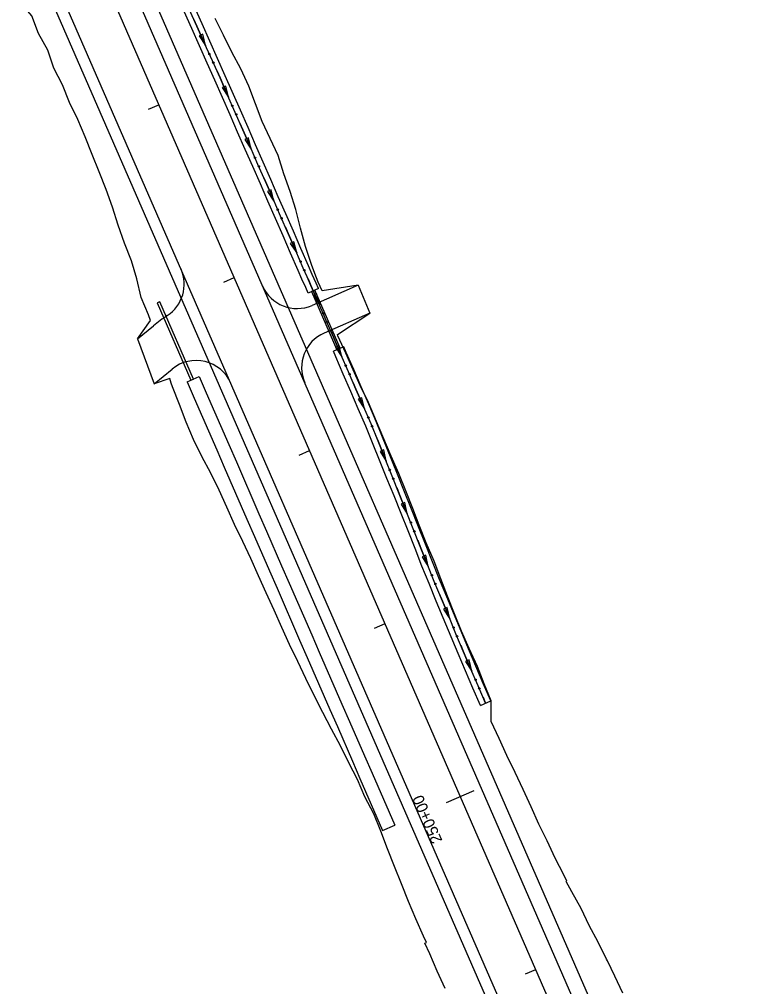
# Model space of a CAD drawing. Extents: x 948761 to 996004, y 1858548 to 1925175.
# Drawn here: x 964875 to 965260, y 1899394 to 1899906 of the extents above; entities that cross this region are included whole.
import ezdxf

# ---------------------------------------------------------------- set-up
doc = ezdxf.new("R2010")
doc.units = 0
for name, color, linetype in [('62', 7, 'Continuous'), ('R_Drainage', 7, 'Continuous'), ('R_Horz Alg', 7, 'Continuous'), ('R_Horz Alg Annot', 7, 'Continuous'), ('R_Proposed Const Limits', 7, 'Continuous'), ('R_Proposed Road', 7, 'Continuous')]:
    doc.layers.add(name, color=color, linetype=linetype)

msp = doc.modelspace()

# ---------------------------------------------------------------- linework, layer by layer
at = {"layer": '62'}
for p, q in [((964972.07, 1899898.53), (964970.13, 1899897.67)), ((964970.13, 1899897.67), (964973.56, 1899892.63)), ((964973.56, 1899892.63), (964972.07, 1899898.53)), ((964984.3, 1899871.09), (964982.36, 1899870.24)), ((964985.75, 1899865.17), (964984.3, 1899871.09)), ((964982.36, 1899870.24), (964985.75, 1899865.17)), ((964996.38, 1899843.59), (964994.45, 1899842.74)), ((964994.45, 1899842.74), (964997.83, 1899837.67)), ((964997.83, 1899837.67), (964996.38, 1899843.59)), ((965008.42, 1899816.07), (965006.48, 1899815.22)), ((965006.48, 1899815.22), (965009.85, 1899810.14)), ((965009.85, 1899810.14), (965008.42, 1899816.07)), ((965020.45, 1899788.54), (965018.51, 1899787.69)), ((965021.88, 1899782.62), (965020.45, 1899788.54)), ((965018.51, 1899787.69), (965021.88, 1899782.62)), ((965033.41, 1899763.74), (965027.91, 1899761.34)), ((965032.48, 1899761.02), (965030.54, 1899760.17)), ((965030.54, 1899760.17), (965033.9, 1899755.09)), ((965033.9, 1899755.09), (965032.48, 1899761.02)), ((965046.82, 1899732.91), (965041.31, 1899730.52)), ((965044.46, 1899733.47), (965042.52, 1899732.63)), ((965042.52, 1899732.63), (965045.88, 1899727.55)), ((965045.88, 1899727.55), (965044.46, 1899733.47)), ((964963.78, 1899714.27), (964970.19, 1899717.06)), ((965056.42, 1899705.92), (965054.48, 1899705.07)), ((965054.48, 1899705.07), (965057.83, 1899699.99)), ((965057.83, 1899699.99), (965056.42, 1899705.92)), ((965068.03, 1899678.19), (965066.06, 1899677.39)), ((965066.06, 1899677.39), (965069.29, 1899672.23)), ((965069.29, 1899672.23), (965068.03, 1899678.19)), ((965079.27, 1899650.33), (965077.3, 1899649.54)), ((965080.51, 1899644.36), (965079.27, 1899650.33)), ((965077.3, 1899649.54), (965080.51, 1899644.36)), ((965090.38, 1899622.42), (965088.41, 1899621.63)), ((965088.41, 1899621.63), (965091.61, 1899616.45)), ((965091.61, 1899616.45), (965090.38, 1899622.42)), ((965101.71, 1899594.62), (965099.76, 1899593.81)), ((965099.76, 1899593.81), (965103.04, 1899588.67)), ((965103.04, 1899588.67), (965101.71, 1899594.62)), ((965113.28, 1899566.9), (965111.33, 1899566.07)), ((965111.33, 1899566.07), (965114.66, 1899560.97)), ((965114.66, 1899560.97), (965113.28, 1899566.9)), ((965119.26, 1899542.81), (965124.77, 1899545.19)), ((965067.41, 1899476.56), (965073.82, 1899479.35))]:
    msp.add_line(p, q, dxfattribs=at)
for points in [[(965122.01, 1899544), (965118.04, 1899553.18), (965114.07, 1899562.35), (965110.14, 1899571.55), (965106.31, 1899580.79), (965102.47, 1899590.03), (965098.64, 1899599.26), (965094.81, 1899608.5), (965091.08, 1899617.78), (965087.38, 1899627.08), (965083.68, 1899636.38), (965079.99, 1899645.68), (965076.28, 1899654.97), (965072.52, 1899664.24), (965068.77, 1899673.51), (965065.02, 1899682.79), (965061.27, 1899692.06), (965057.29, 1899701.24), (965053.31, 1899710.41), (965049.33, 1899719.58), (965045.35, 1899728.76), (965041.37, 1899737.93), (965037.38, 1899747.1), (965036.58, 1899748.93), (965033.39, 1899756.27), (965029.4, 1899765.44), (965027.4, 1899770.02), (965025.39, 1899774.6), (965021.38, 1899783.76), (965017.38, 1899792.92), (965013.37, 1899802.09), (965009.37, 1899811.25), (965005.37, 1899820.42), (965001.37, 1899829.58), (964997.36, 1899838.74), (964993.34, 1899847.9), (964989.31, 1899857.05), (964985.29, 1899866.21), (964981.27, 1899875.36), (964977.2, 1899884.5), (964973.11, 1899893.62), (964969.01, 1899902.75), (964964.92, 1899911.87)], [(965033.41, 1899763.74), (965032.15, 1899766.64), (965030.14, 1899771.22), (965028.14, 1899775.8), (965024.13, 1899784.96), (965020.12, 1899794.13), (965016.12, 1899803.29), (965012.12, 1899812.45), (965008.12, 1899821.62), (965004.12, 1899830.78), (965000.11, 1899839.95), (964996.08, 1899849.1), (964992.06, 1899858.26), (964984.01, 1899876.58), (964979.94, 1899885.72), (964975.85, 1899894.85), (964971.75, 1899903.98), (964967.66, 1899913.1)], [(965027.91, 1899761.34), (965026.65, 1899764.24), (965024.65, 1899768.82), (965022.64, 1899773.4), (965018.63, 1899782.56), (965014.63, 1899791.72), (965010.62, 1899800.88), (965006.62, 1899810.05), (965002.62, 1899819.21), (964998.62, 1899828.38), (964994.61, 1899837.54), (964990.59, 1899846.69), (964986.57, 1899855.85), (964978.53, 1899874.15), (964974.46, 1899883.27), (964970.37, 1899892.4), (964966.28, 1899901.52), (964962.18, 1899910.65)], [(964967.4, 1899906.35), (964967.42, 1899906.31)], [(964967.42, 1899906.31), (964969.01, 1899902.75), (964973.11, 1899893.62), (964973.56, 1899892.63)], [(964979.68, 1899878.93), (964979.7, 1899878.9)], [(964979.7, 1899878.9), (964981.27, 1899875.36), (964985.29, 1899866.21), (964985.75, 1899865.17)], [(964991.78, 1899851.44), (964991.8, 1899851.41)], [(964991.8, 1899851.41), (964993.34, 1899847.9), (964997.36, 1899838.74), (964997.83, 1899837.67)], [(965003.83, 1899823.93), (965003.85, 1899823.89)], [(965003.85, 1899823.89), (965005.37, 1899820.42), (965009.37, 1899811.25), (965009.85, 1899810.14)], [(965015.86, 1899796.4), (965015.87, 1899796.36)], [(965015.87, 1899796.36), (965017.38, 1899792.92), (965021.38, 1899783.76), (965021.88, 1899782.62)], [(965027.89, 1899768.88), (965027.91, 1899768.85)], [(965027.91, 1899768.84), (965029.4, 1899765.44), (965033.39, 1899756.27), (965033.9, 1899755.09)], [(965039.88, 1899741.34), (965039.9, 1899741.3)], [(965039.9, 1899741.3), (965041.37, 1899737.93), (965045.35, 1899728.76), (965045.88, 1899727.55)], [(965124.77, 1899545.19), (965120.79, 1899554.37), (965116.82, 1899563.54), (965112.91, 1899572.71), (965101.41, 1899600.41), (965097.58, 1899609.63), (965093.86, 1899618.9), (965090.17, 1899628.19), (965086.47, 1899637.49), (965082.77, 1899646.79), (965079.06, 1899656.08), (965075.31, 1899665.36), (965064.04, 1899693.22), (965060.05, 1899702.43), (965056.07, 1899711.6), (965052.09, 1899720.78), (965048.1, 1899729.95), (965046.82, 1899732.91)], [(965119.26, 1899542.81), (965115.29, 1899551.98), (965111.31, 1899561.17), (965107.38, 1899570.39), (965095.87, 1899598.11), (965092.03, 1899607.37), (965088.29, 1899616.67), (965084.59, 1899625.97), (965080.9, 1899635.27), (965077.2, 1899644.56), (965073.49, 1899653.85), (965069.74, 1899663.12), (965058.51, 1899690.9), (965054.54, 1899700.04), (965050.56, 1899709.22), (965046.58, 1899718.39), (965042.6, 1899727.56), (965041.31, 1899730.52)], [(964970.19, 1899717.06), (964973.92, 1899708.52), (964985.91, 1899681.02), (964989.9, 1899671.86), (965001.89, 1899644.36), (965005.89, 1899635.19), (965013.88, 1899616.86), (965017.88, 1899607.69), (965029.86, 1899580.19), (965033.86, 1899571.02), (965045.85, 1899543.52), (965049.85, 1899534.36), (965057.84, 1899516.02), (965061.84, 1899506.85), (965073.82, 1899479.35)], [(964963.78, 1899714.27), (964967.5, 1899705.73), (964979.49, 1899678.23), (964983.49, 1899669.06), (964995.47, 1899641.56), (964999.47, 1899632.39), (965007.46, 1899614.06), (965011.46, 1899604.89), (965023.45, 1899577.39), (965027.45, 1899568.23), (965039.43, 1899540.72), (965043.43, 1899531.56), (965051.42, 1899513.22), (965055.42, 1899504.06), (965067.41, 1899476.56)], [(965051.85, 1899713.79), (965051.86, 1899713.75)], [(965051.86, 1899713.75), (965053.31, 1899710.41), (965057.29, 1899701.24), (965057.83, 1899699.99)], [(965063.66, 1899686.17), (965063.67, 1899686.13)], [(965063.67, 1899686.13), (965065.02, 1899682.79), (965068.77, 1899673.51), (965069.29, 1899672.23)], [(965074.92, 1899658.32), (965074.93, 1899658.29)], [(965074.93, 1899658.29), (965076.28, 1899654.97), (965079.99, 1899645.68), (965080.51, 1899644.36)], [(965086.05, 1899630.42), (965086.07, 1899630.39)], [(965086.07, 1899630.39), (965087.38, 1899627.08), (965091.08, 1899617.78), (965091.61, 1899616.45)], [(965097.27, 1899602.56), (965097.29, 1899602.52)], [(965097.29, 1899602.52), (965098.64, 1899599.26), (965102.47, 1899590.03), (965103.04, 1899588.67)], [(965108.79, 1899574.82), (965108.8, 1899574.78)], [(965108.8, 1899574.78), (965110.14, 1899571.55), (965114.07, 1899562.35), (965114.66, 1899560.97)], [(965120.62, 1899547.21), (965120.64, 1899547.17)], [(965120.64, 1899547.17), (965122.01, 1899544)]]:
    msp.add_lwpolyline(points, dxfattribs=at)
for centre in [(964975.64, 1899888.07), (964977.69, 1899883.5), (964987.79, 1899860.6), (964989.81, 1899856.02), (964999.87, 1899833.1), (965001.87, 1899828.51), (965011.89, 1899805.57), (965013.89, 1899800.98), (965023.92, 1899778.05), (965025.93, 1899773.46), (965035.93, 1899750.52), (965037.93, 1899745.92), (965047.9, 1899722.97), (965049.9, 1899718.37), (965059.86, 1899695.41), (965061.82, 1899690.8), (965071.2, 1899667.6), (965073.08, 1899662.95), (965082.39, 1899639.72), (965084.24, 1899635.07), (965093.51, 1899611.82), (965095.39, 1899607.18), (965104.99, 1899584.06), (965106.91, 1899579.43), (965116.68, 1899556.39), (965118.68, 1899551.8)]:
    msp.add_circle(centre, 0.375, dxfattribs=at)
at = {"layer": 'R_Drainage'}
for p, q in [((965031.58, 1899762.94), (965029.75, 1899762.14)), ((965044.98, 1899732.12), (965031.58, 1899762.94)), ((965029.75, 1899762.14), (965043.15, 1899731.32)), ((964949.36, 1899756.72), (964947.98, 1899756.12)), ((964947.98, 1899756.12), (964965.84, 1899715.17)), ((964967.21, 1899715.77), (964949.36, 1899756.72)), ((965043.15, 1899731.32), (965044.98, 1899732.12)), ((964965.84, 1899715.17), (964967.21, 1899715.77))]:
    msp.add_line(p, q, dxfattribs=at)
at = {"layer": 'R_Horz Alg'}
msp.add_line((965242.02, 1899188.63), (964906.4, 1899958.5), dxfattribs=at)
at = {"layer": 'R_Horz Alg Annot'}
for points in [[(964943.31, 1899858.81), (964948.81, 1899861.21)], [(964983.27, 1899767.15), (964988.77, 1899769.54)], [(965023.23, 1899675.48), (965028.73, 1899677.88)], [(965063.2, 1899583.81), (965068.7, 1899586.21)], [(965101.32, 1899491.34), (965115.99, 1899497.74)], [(965143.12, 1899400.47), (965148.62, 1899402.87)]]:
    msp.add_lwpolyline(points, dxfattribs=at)
at = {"layer": 'R_Proposed Const Limits'}
for points in [[(964913.41, 1899834.87), (964909.82, 1899844.21), (964905.89, 1899853.41), (964901.53, 1899862.42), (964897.69, 1899871.65), (964893.15, 1899880.58), (964889.93, 1899890.09), (964885.04, 1899898.86), (964881.5, 1899908.23), (964874.9, 1899915.92)], [(965054.55, 1899765.49), (965035.36, 1899762.51), (965033.35, 1899767.16), (965031.47, 1899771.79), (965029.71, 1899776.48), (965026.59, 1899786.03), (965023.95, 1899795.79), (965021.45, 1899805.61), (965018.46, 1899815.21), (965015.05, 1899824.64), (965012.04, 1899834.23), (965007.84, 1899843.31), (965003.55, 1899852.35), (965000.09, 1899861.75), (964996.48, 1899871.09), (964992.34, 1899880.19), (964987.48, 1899888.98), (964983.18, 1899898.02), (964978.69, 1899906.97)], [(964937.5, 1899737.02), (964944.43, 1899746.81), (964943.41, 1899749.77), (964939.44, 1899758.95), (964937.16, 1899768.86), (964934.31, 1899778.53), (964930.63, 1899787.83), (964927.25, 1899797.27), (964924.18, 1899806.84), (964920.87, 1899816.3), (964917.28, 1899825.65), (964913.41, 1899834.87)], [(965124.94, 1899545.26), (965121.19, 1899554.2), (965117.67, 1899563.43), (965113.22, 1899572.92), (965109.29, 1899582.09), (965105.55, 1899591.37), (965101.89, 1899600.68), (965098.19, 1899609.98), (965094.66, 1899619.34), (965090.58, 1899628.98), (965086.81, 1899638.34), (965083.39, 1899647.16), (965079.71, 1899656.47), (965075.96, 1899665.74), (965072.02, 1899674.93), (965068.08, 1899684.12), (965064.14, 1899693.31), (965059.89, 1899703.33), (965055.46, 1899712.3), (965051.78, 1899720.71), (965047.88, 1899729.52), (965043.75, 1899738.75), (965043.52, 1899739.39), (965060.57, 1899750.66)], [(965100.49, 1899392.8), (965096.42, 1899401.93), (965092.44, 1899411.1), (965089.88, 1899416.85), (965089.88, 1899416.85), (965090.62, 1899417.19), (965089.06, 1899420.54), (965085.02, 1899429.69), (965081.16, 1899438.92), (965077.43, 1899448.2), (965073.69, 1899457.48), (965070.03, 1899466.79), (965066.5, 1899476.16), (965062.74, 1899485.43), (965058.03, 1899494.29), (965054.18, 1899503.52), (965049.55, 1899512.41), (965045.06, 1899521.36), (965040.31, 1899530.2), (965035.71, 1899539.1), (965031.12, 1899548.01), (965026.75, 1899557.01), (965022.41, 1899566.03), (965018.13, 1899575.07), (965014.01, 1899584.19), (965009.88, 1899593.29), (965005.79, 1899602.42), (965001.71, 1899611.55), (964997.58, 1899620.66), (964993.35, 1899629.73), (964988.93, 1899638.71), (964984.83, 1899647.83), (964980.73, 1899656.95), (964976.35, 1899665.95), (964971.63, 1899674.8), (964967.19, 1899683.78), (964963.35, 1899693.01), (964959.73, 1899702.34), (964956.14, 1899711.68), (964955.37, 1899713.53), (964954.65, 1899716.05), (964946.29, 1899713.17)], [(965181.62, 1899417.26), (965176.92, 1899426.12), (965172.63, 1899435.16), (965167.75, 1899443.94), (965164.67, 1899449.45), (965164.66, 1899449.46), (965165.1, 1899449.66), (965163.45, 1899452.97), (965158.85, 1899461.88), (965154.67, 1899470.96), (965150.25, 1899479.95), (965146.17, 1899489.07), (965141.98, 1899498.16), (965137.67, 1899507.19), (965133.27, 1899516.18), (965129.14, 1899525.29), (965124.96, 1899534.37), (965124.94, 1899545.26)], [(965194.79, 1899390.27), (965190.44, 1899399.28), (965186.59, 1899407.34), (965186.11, 1899408.3), (965181.62, 1899417.26)]]:
    msp.add_lwpolyline(points, dxfattribs=at)
at = {"layer": 'R_Proposed Road'}
for p, q in [((965253.02, 1899193.43), (964917.37, 1899963.34)), ((965260.35, 1899196.62), (964924.69, 1899966.58)), ((965220.02, 1899179.04), (964884.44, 1899948.8)), ((965214.52, 1899176.64), (964878.95, 1899946.38)), ((965054.55, 1899765.49), (965030.09, 1899754.83)), ((965054.55, 1899765.49), (965060.57, 1899750.66)), ((965060.57, 1899750.66), (965036.49, 1899740.16)), ((964937.5, 1899737.02), (964945.91, 1899743.94)), ((964937.5, 1899737.02), (964946.29, 1899713.17)), ((964946.29, 1899713.17), (964955.92, 1899721.09))]:
    msp.add_line(p, q, dxfattribs=at)
for centre, radius, start, end in [((964942.28, 1899766.09), 20, 303.4381, 23.5549), ((965022.1, 1899773.16), 20, 203.5549, 293.5549), ((965001.24, 1899676.8), 87, 123.4381, 129.455), ((965044.48, 1899721.83), 20, 113.5549, 203.5549), ((964968.63, 1899705.65), 20, 23.5549, 129.455)]:
    msp.add_arc(centre, radius, start, end, dxfattribs=at)

# ---------------------------------------------------------------- texts
at = {"layer": 'R_Horz Alg Annot'}
msp.add_text('250+00', height=6, rotation=113.5549, dxfattribs=at).set_placement((965099.21, 1899471.17))

doc.saveas('drawing.dxf')
